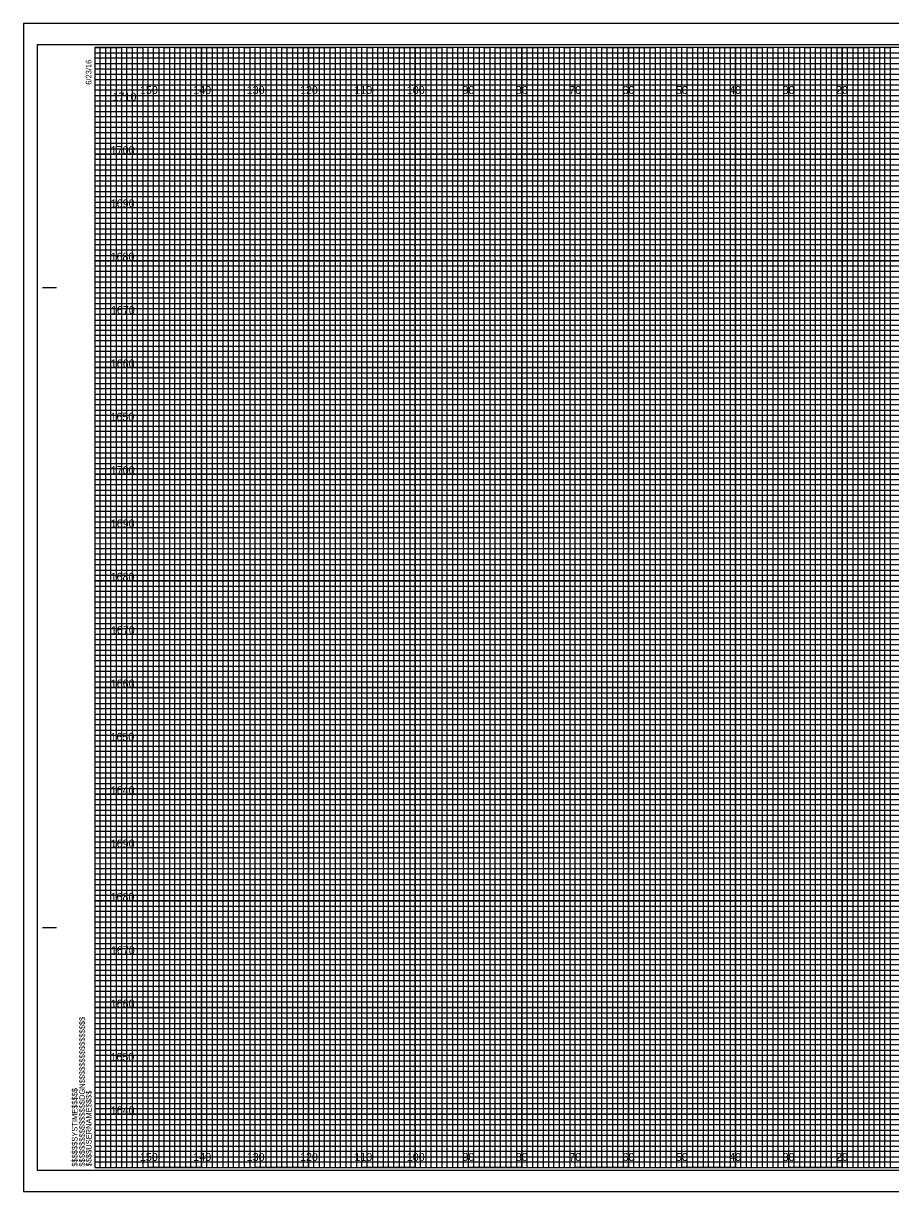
# Model space of a CAD drawing. Extents: x -13 to 1780, y -15 to 3284.
# Drawn here: x 365.9 to 528.4, y 653.4 to 872.4 of the extents above; entities that cross this region are included whole.
import ezdxf

# ---------------------------------------------------------------- set-up
doc = ezdxf.new("R2010")
doc.units = 0
for name, color, linetype in [('Prop Retaining Wall', 7, 'Continuous'), ('Prop SS Cut Line', 7, 'Continuous'), ('Prop SS Fill Line', 7, 'Continuous'), ('Prop SS Transition Line', 7, 'Continuous'), ('Prop XS Earthwork Shape', 7, 'Continuous'), ('Prop XS Noise Wall', 7, 'Continuous'), ('Prop XS Station Labels', 7, 'Continuous'), ('Raster_Level_0', 7, 'Continuous'), ('Scratch_Level_3', 7, 'Continuous'), ('Scratch_Level_7', 7, 'Continuous'), ('Typical Bridge Rail CELL', 7, 'Continuous')]:
    doc.layers.add(name, color=color, linetype=linetype)

msp = doc.modelspace()

# ---------------------------------------------------------------- linework, layer by layer
at = {"layer": 'Prop Retaining Wall'}
for p, q in [((369.46, 822.94), (371.96, 822.94)), ((369.56, 822.94), (372.06, 822.94)), ((369.46, 702.94), (371.96, 702.94)), ((369.56, 702.94), (372.06, 702.94)), ((379.26, 657.94), (379.26, 657.94)), ((379.26, 657.94), (379.26, 657.94)), ((379.26, 657.94), (379.26, 657.94)), ((379.26, 657.94), (379.26, 657.94)), ((379.26, 657.94), (379.26, 657.94)), ((379.26, 657.94), (379.26, 657.94)), ((379.26, 657.94), (379.26, 657.94))]:
    msp.add_line(p, q, dxfattribs=at)
msp.add_lwpolyline([(699.26, 867.94), (379.26, 867.94), (379.26, 657.94), (699.26, 657.94)], close=True, dxfattribs=at)
at = {"layer": 'Prop SS Cut Line'}
for points in [[(379.26, 867.94), (384.26, 867.94), (384.26, 657.94), (394.26, 657.94), (394.26, 867.94), (404.26, 867.94), (404.26, 657.94), (414.26, 657.94), (414.26, 867.94), (424.26, 867.94), (424.26, 657.94), (434.26, 657.94), (434.26, 867.94), (444.26, 867.94), (444.26, 657.94), (454.26, 657.94), (454.26, 867.94), (464.26, 867.94), (464.26, 657.94), (474.26, 657.94), (474.26, 867.94), (484.26, 867.94), (484.26, 657.94), (494.26, 657.94), (494.26, 867.94), (504.26, 867.94), (504.26, 657.94), (514.26, 657.94), (514.26, 867.94), (524.26, 867.94), (524.26, 657.94), (534.26, 657.94)], [(379.26, 862.94), (654.26, 862.94)], [(379.26, 842.94), (699.26, 842.94), (699.26, 852.94), (379.26, 852.94)], [(379.26, 822.94), (699.26, 822.94), (699.26, 832.94), (379.26, 832.94)], [(379.26, 802.94), (699.26, 802.94), (699.26, 812.94), (379.26, 812.94)], [(379.26, 782.94), (699.26, 782.94), (699.26, 792.94), (379.26, 792.94)], [(379.26, 762.94), (699.26, 762.94), (699.26, 772.94), (379.26, 772.94)], [(379.26, 742.94), (699.26, 742.94), (699.26, 752.94), (379.26, 752.94)], [(379.26, 722.94), (699.26, 722.94), (699.26, 732.94), (379.26, 732.94)], [(379.26, 702.94), (699.26, 702.94), (699.26, 712.94), (379.26, 712.94)], [(379.26, 682.94), (699.26, 682.94), (699.26, 692.94), (379.26, 692.94)], [(379.26, 662.94), (699.26, 662.94), (699.26, 672.94), (379.26, 672.94)]]:
    msp.add_lwpolyline(points, dxfattribs=at)
at = {"layer": 'Prop SS Fill Line'}
for p, q in [((389.26, 867.94), (379.26, 867.94)), ((389.26, 657.94), (389.26, 867.94)), ((409.26, 867.94), (399.26, 867.94)), ((399.26, 867.94), (399.26, 657.94)), ((409.26, 657.94), (409.26, 867.94)), ((429.26, 867.94), (419.26, 867.94)), ((419.26, 867.94), (419.26, 657.94)), ((429.26, 657.94), (429.26, 867.94)), ((449.26, 867.94), (439.26, 867.94)), ((439.26, 867.94), (439.26, 657.94)), ((449.26, 657.94), (449.26, 867.94)), ((469.26, 867.94), (459.26, 867.94)), ((459.26, 867.94), (459.26, 657.94)), ((469.26, 657.94), (469.26, 867.94)), ((489.26, 867.94), (479.26, 867.94)), ((479.26, 867.94), (479.26, 657.94)), ((489.26, 657.94), (489.26, 867.94)), ((509.26, 867.94), (499.26, 867.94)), ((499.26, 867.94), (499.26, 657.94)), ((509.26, 657.94), (509.26, 867.94)), ((529.26, 867.94), (519.26, 867.94)), ((519.26, 867.94), (519.26, 657.94)), ((399.26, 657.94), (389.26, 657.94)), ((419.26, 657.94), (409.26, 657.94)), ((439.26, 657.94), (429.26, 657.94)), ((459.26, 657.94), (449.26, 657.94)), ((479.26, 657.94), (469.26, 657.94)), ((499.26, 657.94), (489.26, 657.94)), ((519.26, 657.94), (509.26, 657.94))]:
    msp.add_line(p, q, dxfattribs=at)
for points in [[(379.26, 857.94), (699.26, 857.94), (699.26, 847.94), (379.26, 847.94)], [(379.26, 837.94), (699.26, 837.94), (699.26, 827.94), (379.26, 827.94)], [(379.26, 817.94), (699.26, 817.94), (699.26, 807.94), (379.26, 807.94)], [(379.26, 797.94), (699.26, 797.94), (699.26, 787.94), (379.26, 787.94)], [(379.26, 777.94), (699.26, 777.94), (699.26, 767.94), (379.26, 767.94)], [(379.26, 757.94), (699.26, 757.94), (699.26, 747.94), (379.26, 747.94)], [(379.26, 737.94), (699.26, 737.94), (699.26, 727.94), (379.26, 727.94)], [(379.26, 717.94), (699.26, 717.94), (699.26, 707.94), (379.26, 707.94)], [(379.26, 697.94), (699.26, 697.94), (699.26, 687.94), (379.26, 687.94)], [(379.26, 677.94), (699.26, 677.94), (699.26, 667.94), (379.26, 667.94)]]:
    msp.add_lwpolyline(points, dxfattribs=at)
at = {"layer": 'Prop SS Transition Line'}
for p, q in [((379.26, 866.94), (639.26, 866.94)), ((639.26, 865.92), (379.26, 865.92)), ((379.26, 865.92), (379.26, 864.94)), ((379.26, 864.94), (639.26, 864.94)), ((639.26, 863.83), (379.26, 863.83)), ((379.26, 863.83), (379.26, 861.94)), ((379.26, 861.94), (699.26, 861.94))]:
    msp.add_line(p, q, dxfattribs=at)
for points in [[(379.26, 860.94), (649.26, 860.94), (699.26, 860.94), (699.26, 859.94), (379.26, 859.94)], [(379.26, 858.94), (699.26, 858.94), (699.26, 856.94), (379.26, 856.94)], [(379.26, 855.94), (699.26, 855.94), (699.26, 854.94), (379.26, 854.92)], [(379.26, 853.94), (699.26, 853.94), (699.26, 851.94), (379.26, 851.94)], [(379.26, 850.94), (699.26, 850.94), (699.26, 849.94), (379.26, 849.94)], [(379.26, 848.94), (699.26, 848.94), (699.26, 846.94), (379.26, 846.94)], [(379.26, 845.94), (699.26, 845.94), (699.26, 844.94), (379.26, 844.94)], [(379.26, 843.94), (699.26, 843.94), (699.26, 841.94), (379.26, 841.94)], [(379.26, 840.94), (699.26, 840.94), (699.26, 839.94), (379.26, 839.94)], [(379.26, 838.94), (699.26, 838.94), (699.26, 836.94), (379.26, 836.94)], [(379.26, 835.94), (699.26, 835.94), (699.26, 834.94), (379.26, 834.94)], [(379.26, 833.94), (699.26, 833.94), (699.26, 831.89), (699.26, 830.94), (699.26, 829.94), (379.26, 829.94)], [(379.26, 831.94), (699.26, 831.94), (699.26, 830.94), (379.26, 830.94)], [(379.26, 828.94), (699.26, 828.94), (699.26, 826.94), (379.26, 826.97)], [(379.26, 826.97), (699.26, 826.94), (699.26, 825.94), (379.26, 825.94)], [(379.26, 824.94), (699.26, 824.94), (699.26, 823.94), (379.26, 823.94)], [(379.26, 821.94), (699.26, 821.94), (699.26, 820.94), (379.26, 820.94)], [(379.26, 819.94), (699.26, 819.94), (699.26, 818.94), (379.26, 818.94)], [(379.19, 816.83), (699.26, 816.83), (699.26, 815.82), (379.19, 815.82)], [(379.26, 814.94), (699.26, 814.94), (699.26, 813.94), (379.26, 813.94)], [(379.26, 811.94), (699.26, 811.94), (699.26, 810.94), (379.26, 810.94)], [(379.26, 809.94), (699.26, 809.94), (699.26, 808.94), (379.26, 808.94)], [(379.26, 806.94), (699.26, 806.94), (699.26, 805.94), (379.26, 805.94)], [(379.26, 804.94), (699.26, 804.94), (699.26, 803.94), (379.26, 803.94)], [(379.26, 801.94), (699.26, 801.94), (699.26, 800.94), (379.26, 800.94)], [(379.26, 799.94), (699.26, 799.94), (699.26, 798.94), (379.26, 798.94)], [(379.26, 796.94), (699.26, 796.94), (699.25, 795.92), (379.26, 795.94)], [(379.26, 794.94), (699.26, 794.94), (699.26, 793.94), (379.26, 793.94)], [(379.26, 791.94), (699.26, 791.94), (699.26, 790.94), (379.26, 790.94)], [(379.26, 789.94), (699.26, 789.94), (699.26, 788.94), (379.26, 788.94)], [(379.26, 786.94), (699.26, 786.94), (699.26, 785.94), (379.26, 785.94)], [(379.26, 784.94), (699.26, 784.94), (699.26, 783.94), (379.26, 783.94)], [(379.26, 781.94), (699.26, 781.94), (699.26, 780.94), (379.26, 780.94)], [(379.26, 779.94), (699.26, 779.94), (699.26, 778.94), (379.26, 778.94)], [(379.26, 776.94), (699.26, 776.94), (699.26, 775.94), (379.26, 775.94)], [(379.26, 774.93), (699.33, 774.85), (699.26, 773.94), (379.26, 773.94)], [(379.26, 771.94), (699.26, 771.94), (699.26, 770.94), (379.26, 770.94)], [(379.26, 769.94), (699.26, 769.94), (699.26, 768.94), (379.26, 768.94)], [(379.26, 766.94), (699.26, 766.94), (699.26, 765.94), (379.26, 765.94)], [(379.26, 764.94), (699.26, 764.94), (699.26, 763.94), (379.26, 763.94)], [(379.26, 761.94), (699.26, 761.94), (699.26, 760.94), (379.26, 760.94)], [(379.26, 759.94), (699.26, 759.94), (699.26, 758.94), (379.26, 758.94)], [(379.26, 756.94), (699.26, 756.94), (699.26, 755.94), (379.26, 755.94)], [(379.26, 754.94), (699.26, 754.94), (699.26, 753.94), (379.26, 753.94)], [(379.26, 751.94), (699.26, 751.94), (699.26, 750.94), (379.26, 750.94)], [(379.26, 749.94), (699.26, 749.94), (699.26, 748.94), (379.26, 748.94)], [(379.26, 746.94), (699.26, 746.94), (699.26, 745.94), (379.26, 745.94)], [(379.26, 744.94), (699.26, 744.94), (699.26, 743.94), (379.26, 743.94)], [(379.26, 741.94), (699.26, 741.94), (699.26, 740.94), (379.26, 740.94)], [(379.26, 739.94), (699.26, 739.94), (699.26, 738.94), (379.26, 738.94)], [(379.26, 736.94), (699.26, 736.94), (699.25, 735.92), (379.26, 735.94)], [(379.26, 734.94), (699.26, 734.94), (699.26, 733.94), (379.26, 733.94)], [(379.26, 731.94), (699.26, 731.94), (699.26, 730.94), (379.26, 730.94)], [(379.26, 729.94), (699.26, 729.94), (699.26, 728.94), (379.26, 728.94)], [(379.26, 726.94), (699.26, 726.94), (699.26, 725.94), (379.26, 725.94)], [(379.26, 724.94), (699.26, 724.94), (699.26, 723.94), (379.26, 723.94)], [(379.26, 721.94), (699.26, 721.94), (699.26, 720.94), (379.26, 720.94)], [(379.26, 719.94), (699.26, 719.94), (699.26, 718.94), (379.26, 718.94)], [(379.26, 716.94), (699.26, 716.94), (699.26, 715.94), (379.26, 715.94)], [(379.26, 714.93), (699.33, 714.85), (699.26, 713.94), (379.26, 713.94)], [(379.26, 711.94), (699.26, 711.94), (699.26, 710.94), (379.26, 710.94)], [(379.26, 709.94), (699.26, 709.94), (699.26, 708.94), (379.26, 708.94)], [(379.26, 706.94), (699.26, 706.94), (699.26, 705.94), (379.26, 705.94)], [(379.26, 704.94), (699.26, 704.94), (699.26, 703.94), (379.26, 703.94)], [(379.26, 701.94), (699.26, 701.94), (699.26, 700.94), (379.26, 700.94)], [(379.26, 699.94), (699.26, 699.94), (699.26, 698.94), (379.26, 698.94)], [(379.26, 696.94), (699.26, 696.94), (699.26, 695.94), (379.26, 695.94)], [(379.26, 694.94), (699.26, 694.94), (699.26, 693.94), (379.26, 693.94)], [(379.26, 691.94), (699.26, 691.94), (699.26, 690.94), (379.26, 690.94)], [(379.26, 689.94), (699.26, 689.94), (699.26, 688.94), (379.26, 688.94)], [(379.26, 686.94), (699.26, 686.94), (699.26, 685.94), (379.26, 685.94)], [(379.26, 684.94), (699.26, 684.94), (699.26, 683.94), (379.26, 683.94)], [(379.26, 681.94), (699.26, 681.94), (699.26, 680.94), (379.26, 680.94)], [(379.26, 679.94), (699.26, 679.94), (699.26, 678.94), (379.26, 678.94)], [(379.26, 676.94), (699.26, 676.94), (699.26, 675.94), (379.26, 675.94)], [(379.26, 674.94), (699.26, 674.94), (699.26, 673.94), (379.26, 673.94)], [(379.26, 671.94), (699.26, 671.94), (699.26, 670.94), (379.26, 670.94)], [(379.26, 669.94), (699.26, 669.94), (699.26, 668.94), (379.26, 668.94)], [(379.26, 666.94), (699.26, 666.94), (699.26, 665.94), (379.26, 665.94)], [(379.26, 664.94), (699.26, 664.94), (699.26, 663.94), (379.26, 663.94)], [(379.26, 661.94), (699.26, 661.94), (699.26, 660.94), (379.26, 660.94)], [(379.26, 659.94), (699.26, 659.94), (699.26, 658.94), (379.26, 658.94)]]:
    msp.add_lwpolyline(points, dxfattribs=at)
at = {"layer": 'Prop XS Earthwork Shape'}
msp.add_lwpolyline([(365.86, 653.44), (702.56, 653.44), (702.56, 872.44), (365.86, 872.44)], close=True, dxfattribs=at)
at = {"layer": 'Prop XS Noise Wall'}
for p, q in [((389.26, 657.94), (389.26, 867.94)), ((399.26, 657.94), (399.26, 867.94)), ((409.26, 657.94), (409.26, 867.94)), ((419.26, 657.94), (419.26, 867.94)), ((429.26, 657.94), (429.26, 867.94)), ((439.26, 657.94), (439.26, 867.94)), ((449.26, 657.94), (449.26, 867.94)), ((459.26, 657.94), (459.26, 867.94)), ((469.26, 657.94), (469.26, 867.94)), ((479.26, 657.94), (479.26, 867.94)), ((489.26, 657.94), (489.26, 867.94)), ((499.26, 657.94), (499.26, 867.94)), ((509.26, 657.94), (509.26, 867.94)), ((519.26, 657.94), (519.26, 867.94)), ((379.26, 857.94), (699.26, 857.94)), ((379.26, 847.94), (699.26, 847.94)), ((379.26, 837.94), (699.26, 837.94)), ((379.26, 827.94), (699.26, 827.94)), ((379.26, 817.94), (699.26, 817.94)), ((379.26, 807.94), (699.26, 807.94)), ((379.26, 797.94), (699.26, 797.94)), ((379.26, 787.94), (699.26, 787.94)), ((379.26, 777.94), (699.26, 777.94)), ((379.26, 767.94), (699.26, 767.94)), ((379.26, 757.94), (699.26, 757.94)), ((379.26, 747.94), (699.26, 747.94)), ((379.26, 737.94), (699.26, 737.94)), ((379.26, 727.94), (699.26, 727.94)), ((379.26, 717.94), (699.26, 717.94)), ((379.26, 707.94), (699.26, 707.94)), ((379.26, 697.94), (699.26, 697.94)), ((379.26, 687.94), (699.26, 687.94)), ((379.26, 677.94), (699.26, 677.94)), ((379.26, 667.94), (699.26, 667.94))]:
    msp.add_line(p, q, dxfattribs=at)
at = {"layer": 'Prop XS Station Labels'}
for p, q in [((702.56, 872.44), (365.86, 872.44)), ((365.86, 872.44), (365.86, 653.44)), ((365.86, 653.44), (702.56, 653.44))]:
    msp.add_line(p, q, dxfattribs=at)
at = {"layer": 'Scratch_Level_7'}
msp.add_lwpolyline([(368.46, 657.44), (701.66, 657.44), (701.66, 868.44), (368.46, 868.44)], close=True, dxfattribs=at)
at = {"layer": 'Typical Bridge Rail CELL'}
for points in [[(379.26, 657.94), (380.26, 657.94), (380.26, 867.94), (381.26, 867.94), (381.26, 657.94)], [(381.26, 657.94), (382.26, 657.94), (382.26, 867.94), (383.26, 867.94), (383.26, 657.94)], [(384.26, 657.94), (385.26, 657.94), (385.26, 867.94), (386.26, 867.94), (386.26, 657.94)], [(386.26, 657.94), (387.26, 657.94), (387.26, 867.94), (388.26, 867.94), (388.26, 657.94)], [(389.26, 657.94), (390.26, 657.94), (390.26, 867.94), (391.26, 867.94), (391.26, 657.94)], [(391.26, 657.94), (392.26, 657.94), (392.26, 867.94), (393.26, 867.94), (393.26, 657.94)], [(394.26, 657.94), (395.26, 657.94), (395.26, 867.94), (396.26, 867.94), (396.26, 657.94)], [(396.26, 657.94), (397.26, 657.94), (397.26, 867.94), (398.26, 867.94), (398.26, 657.94)], [(399.26, 657.94), (400.26, 657.94), (400.26, 867.94), (401.26, 867.94), (401.26, 657.94)], [(401.26, 657.94), (402.26, 657.94), (402.26, 867.94), (403.26, 867.94), (403.26, 657.94)], [(404.26, 657.94), (405.26, 657.94), (405.26, 867.94), (406.26, 867.94), (406.26, 657.94)], [(406.26, 657.94), (407.26, 657.94), (407.26, 867.94), (408.26, 867.94), (408.26, 657.94)], [(409.26, 657.94), (410.26, 657.94), (410.26, 867.94), (411.26, 867.94), (411.26, 657.94)], [(411.26, 657.94), (412.26, 657.94), (412.26, 867.94), (413.26, 867.94), (413.26, 657.94)], [(414.26, 657.94), (415.26, 657.94), (415.26, 867.94), (416.26, 867.94), (416.26, 657.94)], [(416.26, 657.94), (417.26, 657.94), (417.26, 867.94), (418.26, 867.94), (418.26, 657.94)], [(419.26, 657.94), (420.26, 657.94), (420.26, 867.94), (421.26, 867.94), (421.26, 657.94)], [(421.26, 657.94), (422.26, 657.94), (422.26, 867.94), (423.26, 867.94), (423.26, 657.94)], [(424.26, 657.94), (425.26, 657.94), (425.26, 867.94), (426.26, 867.94), (426.26, 657.94)], [(426.26, 657.94), (427.26, 657.94), (427.26, 867.94), (428.26, 867.94), (428.26, 657.94)], [(429.26, 657.94), (430.26, 657.94), (430.26, 867.94), (431.26, 867.94), (431.26, 657.94)], [(431.26, 657.94), (432.26, 657.94), (432.26, 867.94), (433.26, 867.94), (433.26, 657.94)], [(434.26, 657.94), (435.26, 657.94), (435.26, 867.94), (436.26, 867.94), (436.26, 657.94)], [(436.26, 657.94), (437.26, 657.94), (437.26, 867.94), (438.26, 867.94), (438.26, 657.94)], [(439.26, 657.94), (440.26, 657.94), (440.26, 867.94), (441.26, 867.94), (441.26, 657.94)], [(441.26, 657.94), (442.26, 657.94), (442.26, 867.94), (443.26, 867.94), (443.26, 657.94)], [(444.26, 657.94), (445.26, 657.94), (445.26, 867.94), (446.26, 867.94), (446.26, 657.94)], [(446.26, 657.94), (447.26, 657.94), (447.26, 867.94), (448.26, 867.94), (448.26, 657.94)], [(449.26, 657.94), (450.26, 657.94), (450.26, 867.94), (451.26, 867.94), (451.26, 657.94)], [(451.26, 657.94), (452.26, 657.94), (452.26, 867.94), (453.26, 867.94), (453.26, 657.94)], [(454.26, 657.94), (455.26, 657.94), (455.26, 867.94), (456.26, 867.94), (456.26, 657.94)], [(456.26, 657.94), (457.26, 657.94), (457.26, 867.94), (458.26, 867.94), (458.26, 657.94)], [(459.26, 657.94), (460.26, 657.94), (460.26, 867.94), (461.26, 867.94), (461.26, 657.94)], [(461.26, 657.94), (462.26, 657.94), (462.26, 867.94), (463.26, 867.94), (463.26, 657.94)], [(464.26, 657.94), (465.26, 657.94), (465.26, 867.94), (466.26, 867.94), (466.26, 657.94)], [(466.26, 657.94), (467.26, 657.94), (467.26, 867.94), (468.26, 867.94), (468.26, 657.94)], [(469.26, 657.94), (470.26, 657.94), (470.26, 867.94), (471.26, 867.94), (471.26, 657.94)], [(471.26, 657.94), (472.26, 657.94), (472.26, 867.94), (473.26, 867.94), (473.26, 657.94)], [(474.26, 657.94), (475.26, 657.94), (475.26, 867.94), (476.26, 867.94), (476.26, 657.94)], [(476.26, 657.94), (477.26, 657.94), (477.26, 867.94), (478.26, 867.94), (478.26, 657.94)], [(479.26, 657.94), (480.26, 657.94), (480.26, 867.94), (481.26, 867.94), (481.26, 657.94)], [(481.26, 657.94), (482.26, 657.94), (482.26, 867.94), (483.26, 867.94), (483.26, 657.94)], [(484.26, 657.94), (485.26, 657.94), (485.26, 867.94), (486.26, 867.94), (486.26, 657.94)], [(486.26, 657.94), (487.26, 657.94), (487.26, 867.94), (488.26, 867.94), (488.26, 657.94)], [(489.26, 657.94), (490.26, 657.94), (490.26, 867.94), (491.26, 867.94), (491.26, 657.94)], [(491.26, 657.94), (492.26, 657.94), (492.26, 867.94), (493.26, 867.94), (493.26, 657.94)], [(494.26, 657.94), (495.26, 657.94), (495.26, 867.94), (496.26, 867.94), (496.26, 657.94)], [(496.26, 657.94), (497.26, 657.94), (497.26, 867.94), (498.26, 867.94), (498.26, 657.94)], [(499.26, 657.94), (500.26, 657.94), (500.26, 867.94), (501.26, 867.94), (501.26, 657.94)], [(501.26, 657.94), (502.26, 657.94), (502.26, 867.94), (503.26, 867.94), (503.26, 657.94)], [(504.26, 657.94), (505.26, 657.94), (505.26, 867.94), (506.26, 867.94), (506.26, 657.94)], [(506.26, 657.94), (507.26, 657.94), (507.26, 867.94), (508.26, 867.94), (508.26, 657.94)], [(509.26, 657.94), (510.26, 657.94), (510.26, 867.94), (511.26, 867.94), (511.26, 657.94)], [(511.26, 657.94), (512.26, 657.94), (512.26, 867.94), (513.26, 867.94), (513.26, 657.94)], [(514.26, 657.94), (515.26, 657.94), (515.26, 867.94), (516.26, 867.94), (516.26, 657.94)], [(516.26, 657.94), (517.26, 657.94), (517.26, 867.94), (518.26, 867.94), (518.26, 657.94)], [(519.26, 657.94), (520.26, 657.94), (520.26, 867.94), (521.26, 867.94), (521.26, 657.94)], [(521.26, 657.94), (522.26, 657.94), (522.26, 867.94), (523.26, 867.94), (523.26, 657.94)], [(524.26, 657.94), (525.26, 657.94), (525.26, 867.94), (526.26, 867.94), (526.26, 657.94)], [(526.26, 657.94), (527.26, 657.94), (527.26, 867.94), (528.26, 867.94), (528.26, 657.94)]]:
    msp.add_lwpolyline(points, dxfattribs=at)

# ---------------------------------------------------------------- texts
at = {"layer": 'Prop Retaining Wall'}
for s, p in [('6/23/16', (378.61, 860.94)), ('$$$$$$$$$$$$$$$$DGN$$$$$$$$$$$$$$$$', (377.38, 658.12)), ('$$$$$$SYSTIME$$$$$', (376, 658.12)), ('$$$$USERNAME$$$$', (378.64, 658.17))]:
    msp.add_text(s, height=1.05, rotation=90, dxfattribs=at).set_placement(p)
at = {"layer": 'Raster_Level_0'}
for s, p in [('150', (387.7, 859.19)), ('140', (397.7, 859.19)), ('130', (407.7, 859.19)), ('120', (417.7, 859.19)), ('110', (427.88, 859.19)), ('100', (437.7, 859.19)), ('90', (448.12, 859.19)), ('80', (458.12, 859.19)), ('70', (468.12, 859.19)), ('60', (478.12, 859.19)), ('50', (488.12, 859.19)), ('40', (498.12, 859.19)), ('30', (508.12, 859.19)), ('20', (518.12, 859.19)), ('150', (387.7, 659.19)), ('140', (397.7, 659.19)), ('130', (407.7, 659.19)), ('120', (417.7, 659.19)), ('110', (427.88, 659.19)), ('100', (437.7, 659.19)), ('90', (448.12, 659.19)), ('80', (458.12, 659.19)), ('70', (468.12, 659.19)), ('60', (478.12, 659.19)), ('50', (488.12, 659.19)), ('40', (498.12, 659.19)), ('30', (508.12, 659.19)), ('20', (518.12, 659.19))]:
    msp.add_text(s, height=1.5, dxfattribs=at).set_placement(p)
at = {"layer": 'Scratch_Level_3'}
for s, p in [('1710', (382.57, 857.94)), ('1700', (382.24, 847.94)), ('1690', (382.23, 837.94)), ('1680', (382.2, 827.94)), ('1670', (382.26, 817.94)), ('1660', (382.23, 807.94)), ('1650', (382.18, 797.94)), ('1700', (382.24, 787.94)), ('1690', (382.23, 777.94)), ('1680', (382.2, 767.94)), ('1670', (382.26, 757.94)), ('1660', (382.23, 747.94)), ('1650', (382.18, 737.94)), ('1640', (382.23, 727.94)), ('1690', (382.23, 717.94)), ('1680', (382.2, 707.94)), ('1670', (382.26, 697.94)), ('1660', (382.23, 687.94)), ('1650', (382.18, 677.94)), ('1640', (382.23, 667.94))]:
    msp.add_text(s, height=1.5, dxfattribs=at).set_placement(p)

doc.saveas('drawing.dxf')
